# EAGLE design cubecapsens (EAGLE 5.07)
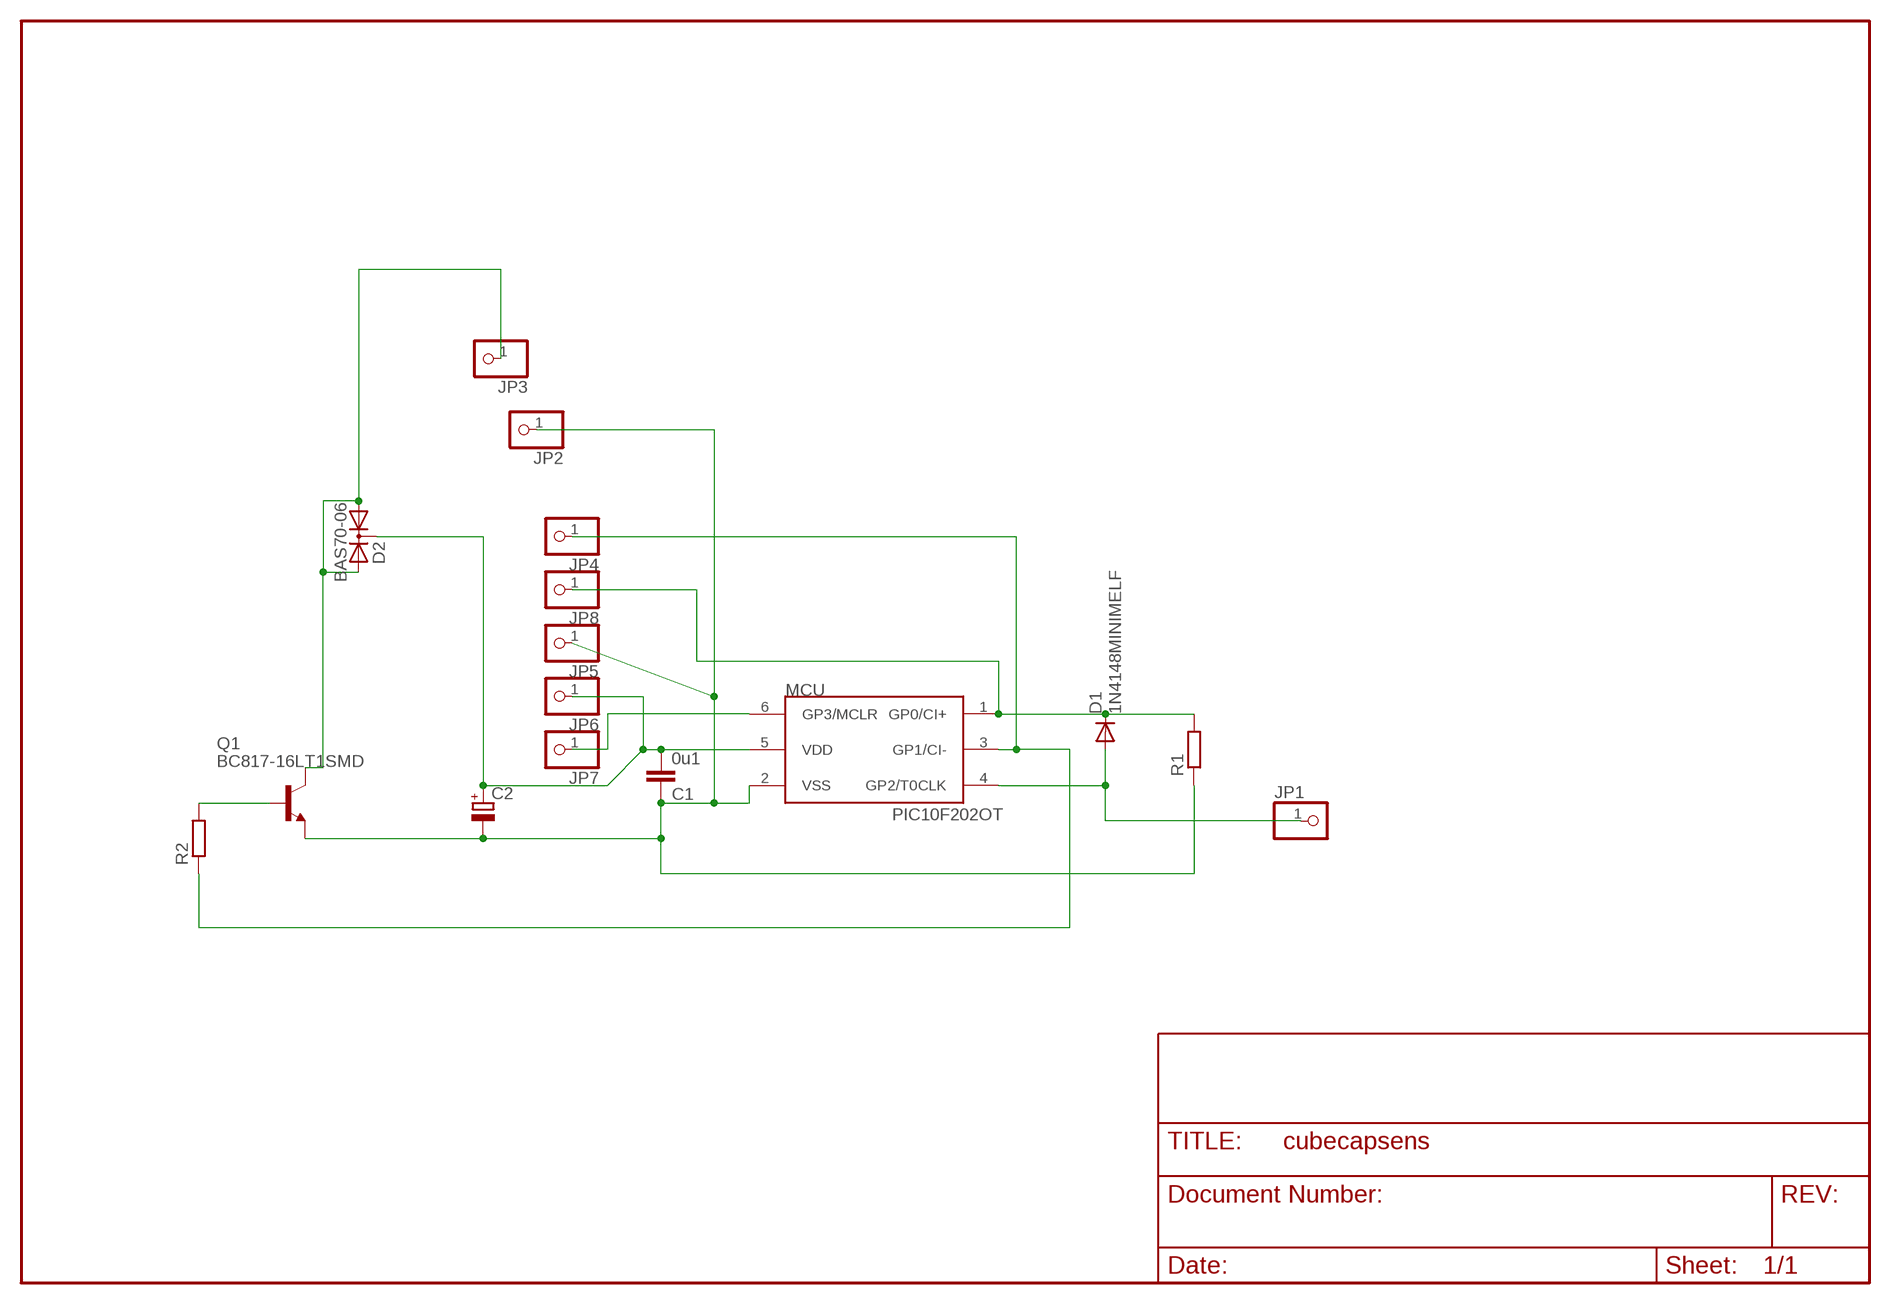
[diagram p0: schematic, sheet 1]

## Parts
C1  0u1  C-EUC1206  [C1206]
C2  CPOL-EUF  [PANASONIC_F]
D1  1N4148MINIMELF  [MINIMELF]
D2  BAS70-06  [SOT23]
JP1  PINHD-1X1  [1X01]
JP2  PINHD-1X1  [1X01]
JP3  PINHD-1X1  [1X01]
JP4  PINHD-1X1  [1X01]
JP5  PINHD-1X1  [1X01]
JP6  PINHD-1X1  [1X01]
JP7  PINHD-1X1  [1X01]
JP8  PINHD-1X1  [1X01]
MCU  PIC10F202OT  [SOT23-6]
Q1  BC817-16LT1SMD  [SOT23-BEC]
R1  R-EU_R1206  [R1206]
R2  R-EU_R1206  [R1206]

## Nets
GP0: D1.C JP8.1 MCU.1(GP0/CI+) R1.2
GP1: JP4.1 MCU.3(GP1/CI-) R2.1
GP2: D1.A JP1.1 MCU.4(GP2/T0CLK)
GP3: JP7.1 MCU.6(GP3/MCLR)
N$1: D2.1(A1) D2.2(A2) JP3.1 Q1.C
N$4: Q1.B R2.2
VDD1: C1.2 C2.+ D2.3(C) JP6.1 MCU.5(VDD)
VSS1: C1.1 C2.- JP2.1 JP5.1 MCU.2(VSS) Q1.E R1.1

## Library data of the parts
C1 = rcl:C-EU: CAPACITOR, European symbol
C2 = rcl-2:CPOL-EU: POLARIZED CAPACITOR, European symbol
D1 = diode-1:1N4148: DIODE
D2 = diode-1:BAS70-06: Silicon Schottky Diodes General-purpose diode for high-speed switching
JP1-JP8 = pinhead(2):PINHD-1X1: PIN HEADER
MCU = microchip-3:PIC10F2*: uPC nW 0,25/0,5k Program Flash memory Comparator
Q1 = transistor-npn:BC817*: NPN Transistor
R1 R2 = rcl-2:R-EU_: RESISTOR, European symbol

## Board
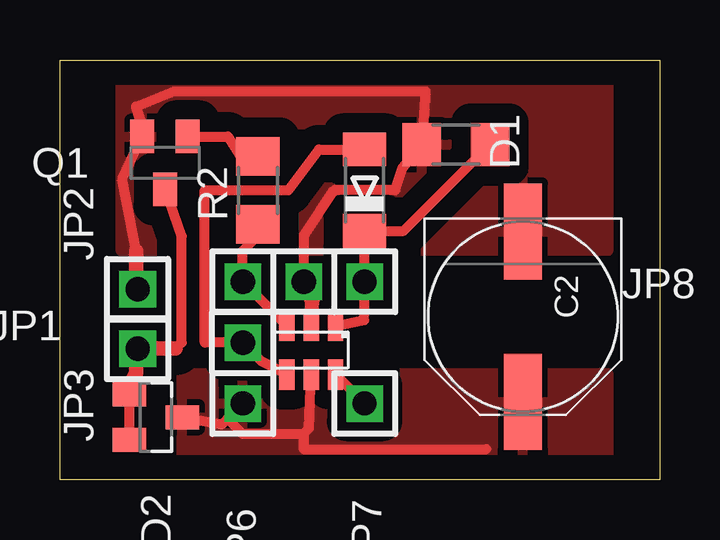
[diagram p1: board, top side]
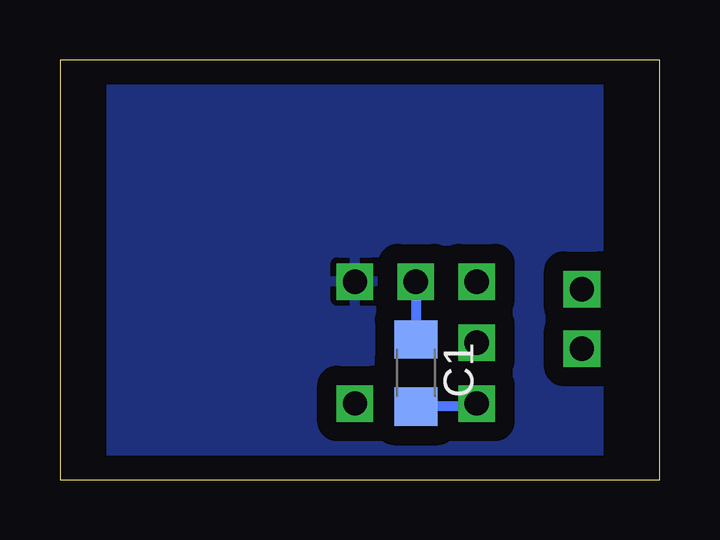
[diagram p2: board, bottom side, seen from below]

Size 25 x 17.5 mm. Coordinates in mm from the lower left corner, seen from the top.
Outline: 0,0 0,17.5 25,17.5 25,0 0,0
Copper layers (1*16): Top 0.035mm / dielectric 1.5mm / Bottom 0.035mm
Design rules "default": minimum track width 10mil, minimum drill 24mil, track to track 8mil, track to pad 8mil, pad to pad 8mil, via to via 8mil, smd to smd 8mil, copper to edge 40mil, drill to drill 8mil, minimum pad ring 10mil, minimum via ring 8mil, stop-mask expansion 4mil, vias tented up to drill 0mil, thermal gap 10mil

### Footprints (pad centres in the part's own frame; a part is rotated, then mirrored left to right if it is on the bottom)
C1206 = smd 1.6 x 1.8: 1 -1.4,0; 2 1.4,0
PANASONIC_F = smd 4 x 1.6: + 3.55,0; - -3.55,0
MINIMELF = smd 1.4 x 1.8: A 1.7,0; C -1.7,0
SOT23 = smd 1 x 1.4: 1 -0.95,-1.1; 2 0.95,-1.1; 3 0,1.1
1X01 = drill 1.016 square: 1 0,0
SOT23-6 = smd 0.635 x 1.27: 1 -1.016,-1.016; 2 0,-1.016; 3 1.016,-1.016; 4 1.016,1.016; 5 0,1.016; 6 -1.016,1.016
SOT23-BEC = smd 1 x 1.4: B -0.95,-1.1; C 0,1.1; E 0.95,-1.1
R1206 = smd 1.6 x 1.803: 1 -1.422,0; 2 1.422,0

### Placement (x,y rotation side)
C1  10.16,4.45 270 bottom
C2  19.3,6.79 270 top
D1  12.7,12.06 90 top
D2  4,2.6 270 top
JP1  7.62,5.71 90 top
JP2  3.24,7.94 90 top
JP3  3.24,5.46 90 top
JP4  7.62,8.26 0 top
JP5  10.16,8.26 0 top
JP6  7.62,3.17 0 top
JP7  12.7,3.17 0 top
JP8  12.7,8.26 0 top
MCU  10.48,5.4 180 top
Q1  4.38,13.21 180 top
R1  16.51,13.97 0 top
R2  8.26,12.06 90 top

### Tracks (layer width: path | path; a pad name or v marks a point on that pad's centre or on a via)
GP0
  Top 0.406: MCU.1 12.68,6.65 12.7,6.99 JP8.1 D1.C 14.33,10.37 R1.2
  pour Bottom (isolate 0.813): 2.54,17.14 22.86,17.14 22.86,-0.64 2.54,-0.64
GP1
  Top 0.406: MCU.3 JP4.1 7.62,9.53 8.74,10.64 R2.1
GP2
  Top 0.406: MCU.4 8.4,4.93 JP1.1 6.03,5.71 6.03,12.06 9.53,12.06 10.79,13.77 D1.A
GP3
  Top 0.406: MCU.6 JP7.1
N$1
  Top 0.406: 4.83,5.46 5.08,5.71 5.08,10.14 Q1.C | 2.86,3.57 3.24,3.57 D2.1 D2.2 | 2.86,3.57 2.86,3.49 | 2.86,3.57 2.86,3.81 | 3.17,5.46 JP3.1
  Top 0.61: JP3.1 4.83,5.46 | 2.86,3.81 3.17,4.45 3.17,5.46
N$4
  Top 0.406: Q1.B 7,14.31 7.62,13.34 8.74,13.34 R2.2
VDD1
  Top 0.406: D2.3 6.73,2.29 6.99,2.54 | 6.99,2.54 JP6.1 | MCU.5 10.38,2.13 10.16,1.91 | 10.16,1.91 7.62,1.91 6.99,2.54 | 19.12,1.97 C2.+ | 17.78,1.27 10.16,1.27 10.16,1.91
  Bottom 0.406: C1.2 7.75,3.04 JP6.1
  pour Top (isolate 0.813): 5.08,4.45 22.86,4.45 22.86,-0.64 5.08,-0.64
VSS1
  Top 0.406: JP2.1 3.17,7.94 | 3.17,9.53 2.6,12.53 Q1.E 3.49,14.56 3.17,15.56 4.76,16.19 15.24,16.19 R1.1 14.29,13.02 13.97,12.06 11.43,12.06 10.16,10.16 JP5.1 10.7,8.16 MCU.2 10.38,8.03
  Top 0.61: 3.17,7.94 3.17,9.53
  Bottom 0.406: JP5.1 C1.1
  pour Top (isolate 0.813): 2.54,9.53 2.54,19.68 22.86,19.68 22.86,9.53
